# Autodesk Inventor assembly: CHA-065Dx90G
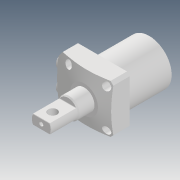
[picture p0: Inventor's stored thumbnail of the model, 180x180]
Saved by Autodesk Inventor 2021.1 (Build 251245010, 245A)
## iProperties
Created: 2019-12
Part Number: CHA-065Dx90G
Description: STEP AP203
Document SubType Name: Assembly
Designer: user
Title: CHA-065Dx90G.STEP
Revision Number: ÈÎºÎ
Sending System: SolidWorks 2017
Preprocessor: SwSTEP 2.0
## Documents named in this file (4)
- D:\Vault_2016\Projekty\Clamptek\Hydraulic\CHA\CHA\CHA-065\Inventor\CHA-065Dx90G\CHA-065Dx90G.iam
- D:\Vault_2016\Projekty\Clamptek\Hydraulic\CHA\CHA\CHA-065\Inventor\CHA-065Dx90G\CHA-065±¾Ìå.ipt
- D:\Vault_2016\Projekty\Clamptek\Hydraulic\CHA\CHA\CHA-065\Inventor\CHA-065Dx90G\CHA-50D(Ë«±Û£©»îÈû¸Ë.ipt
- D:\Vault_2016\Projekty\Clamptek\Hydraulic\CHA\CHA\CHA-065\Inventor\CHA-065Dx90G\G1-4¶ÂÍ·.ipt
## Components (4 placed, 4 different names)
1. CHA-065±¾Ìå_1
2. CHA-50D(Ë«±Û£©»îÈû¸Ë_2
3. G1-4¶ÂÍ·_3
4. G1-4¶ÂÍ·_4
